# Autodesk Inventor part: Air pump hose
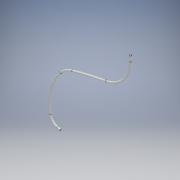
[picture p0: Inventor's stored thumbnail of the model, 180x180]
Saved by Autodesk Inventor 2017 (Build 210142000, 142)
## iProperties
Created: 2020-03
Part Number: Air pump hose
Material: Generic
Document SubType Name: Modeling
Designer: user
Density: 1 g/cm^3
Appearance: Default
Author: user
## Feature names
1. Sweep1
## Parameters: d0 = 342.232 mm, d1 = 32.652 mm, d2 = 55 mm, d5 = 12 mm, d6 = 28.83633 mm, d7 = 6 mm, d8 = 7.2 mm, d9 = 0, d10 = 0
